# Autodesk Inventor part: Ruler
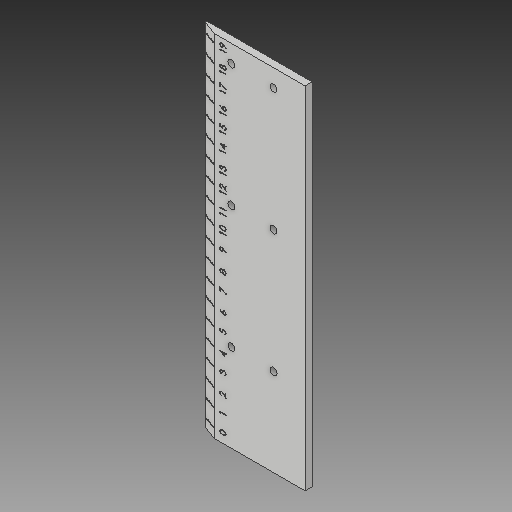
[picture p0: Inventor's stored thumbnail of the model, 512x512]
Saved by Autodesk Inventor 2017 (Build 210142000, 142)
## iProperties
Created: 2020-03
Part Number: Ruler
Material: Generic
Document SubType Name: Modeling
Designer: user
Density: 1 g/cm^3
Appearance: Default
Author: user
Revision Number: ANY
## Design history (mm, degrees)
feature "LPattern2"
body "Solid1"
